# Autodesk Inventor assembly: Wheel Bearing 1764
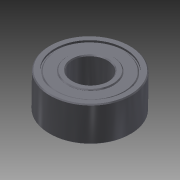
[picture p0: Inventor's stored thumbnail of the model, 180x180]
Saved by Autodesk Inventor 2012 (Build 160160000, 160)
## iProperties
Created: 2009-01
Part Number: Wheel Bearing 1764
Document SubType Name: Assembly
Designer: pmulligan
Author: pmulligan
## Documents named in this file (3)
- R:\CAD Archives\Wheels_1764\Wheel_Bearing_1764\Wheel_Bearing_1764.iam
- R:\CAD Archives\Wheels_1764\Wheel_Bearing_1764\Outer_Casing_1764.ipt
- R:\CAD Archives\Wheels_1764\Wheel_Bearing_1764\Inner_Ring_1764.ipt
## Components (2 placed, 2 different names)
1. Outer_Casing_1764:1 — Mate:1, Mate:2
2. Inner_Ring_1764:1 — Mate:1, Mate:2, Angle:1, Mate:4
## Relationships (4: Mate 3, Angle 1)
- Mate:1: Outer_Casing_1764:1 ↔ Inner_Ring_1764:1
- Mate:2: Outer_Casing_1764:1 ↔ Inner_Ring_1764:1
- Angle:1: Inner_Ring_1764:1
- Mate:4: Inner_Ring_1764:1
